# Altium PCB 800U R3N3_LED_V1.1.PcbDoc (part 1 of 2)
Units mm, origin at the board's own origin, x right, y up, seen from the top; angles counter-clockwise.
Board outline 308.48 x 220.22 mm, 4 copper layers (Top Layer, GND, Mid-Layer 2, Bottom Layer); 79 components, 48 nets, 220 pads, 97 vias.
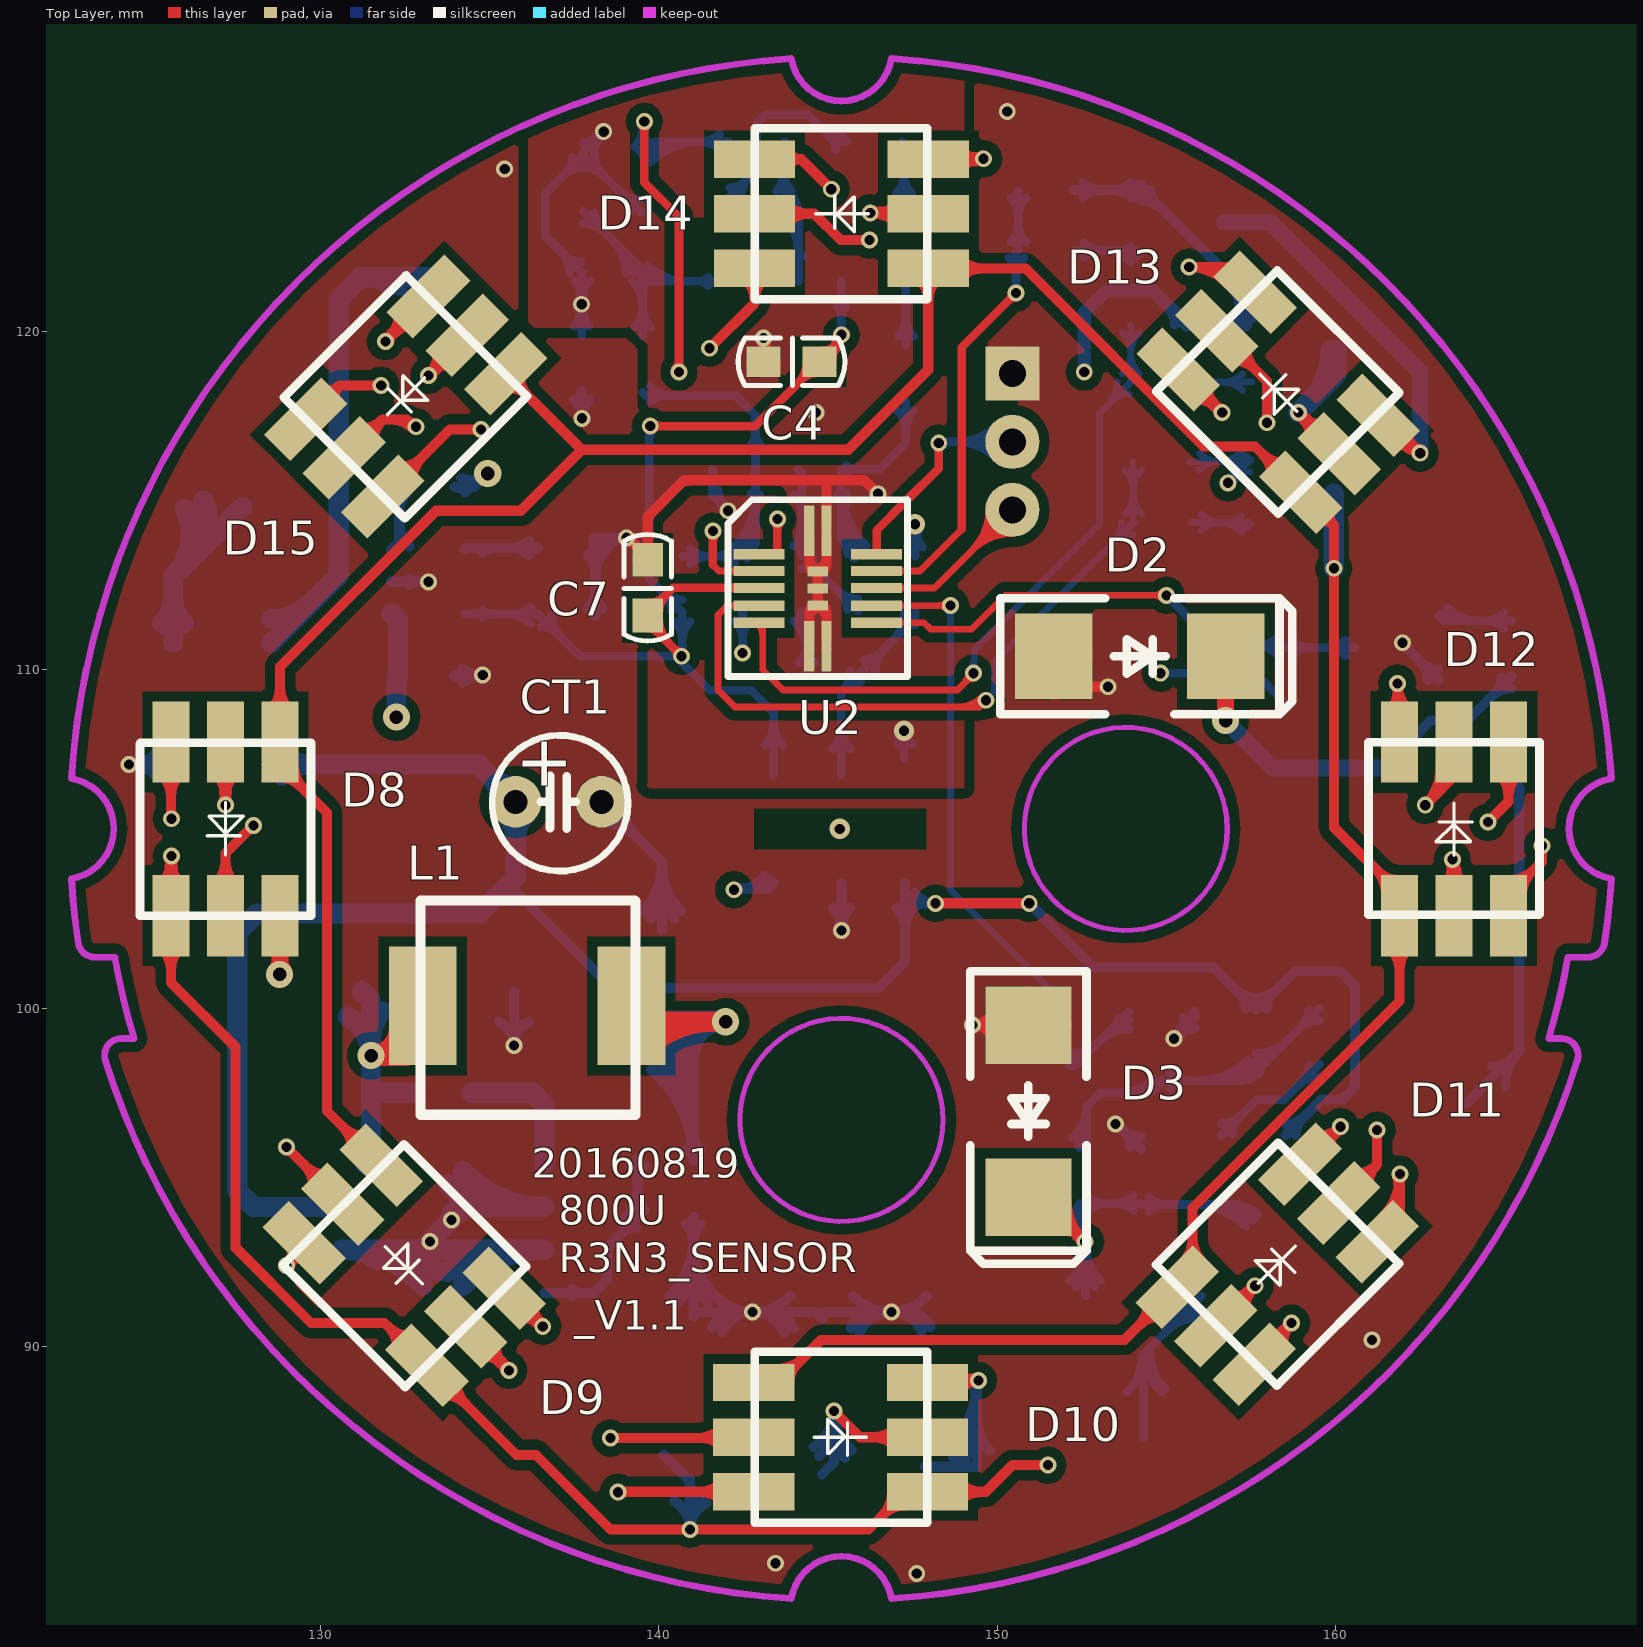
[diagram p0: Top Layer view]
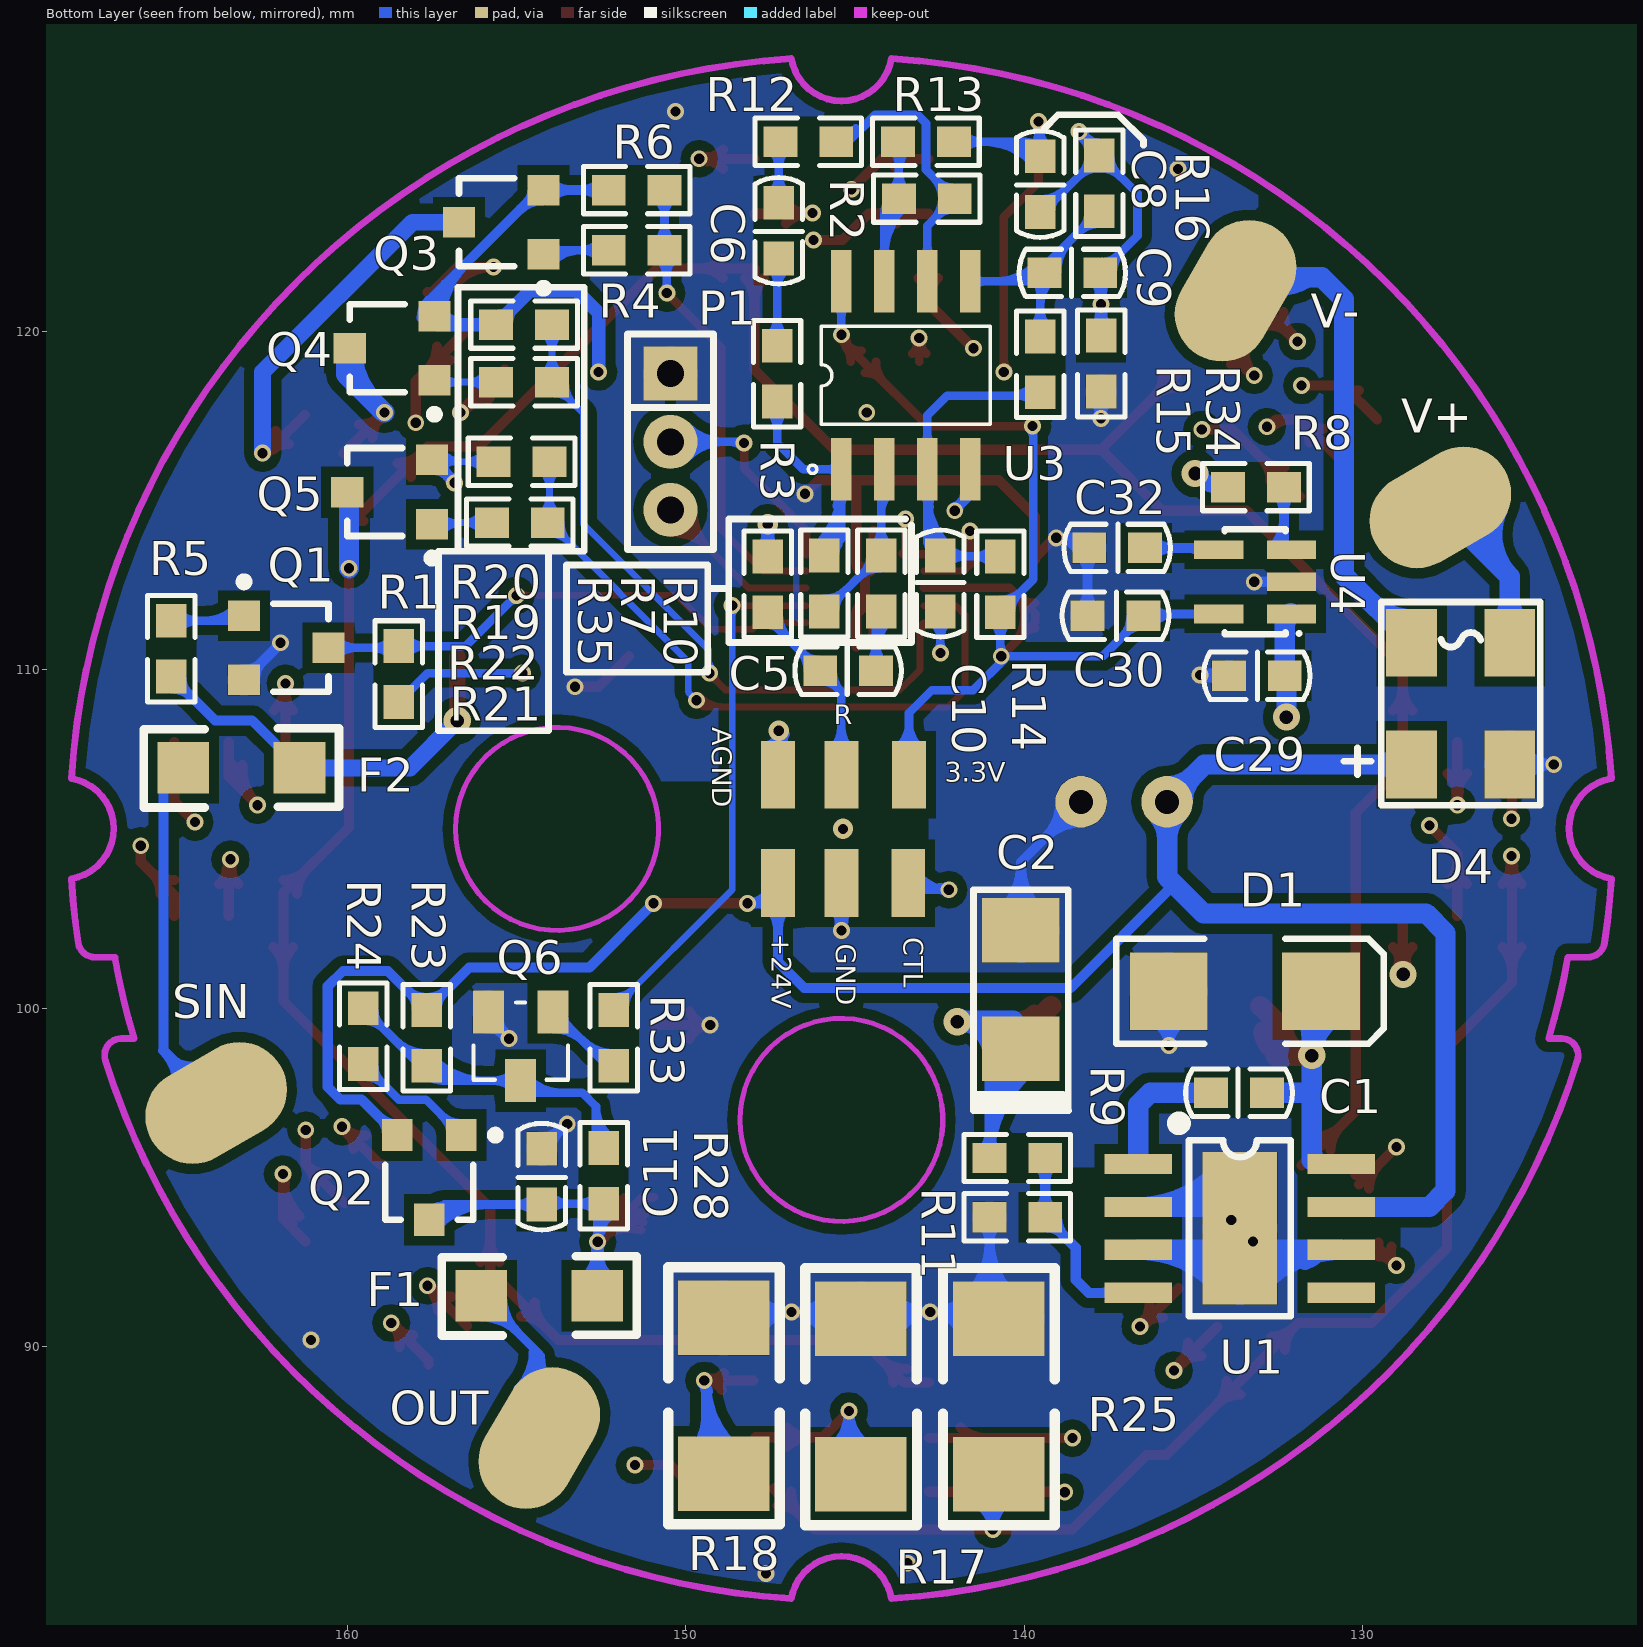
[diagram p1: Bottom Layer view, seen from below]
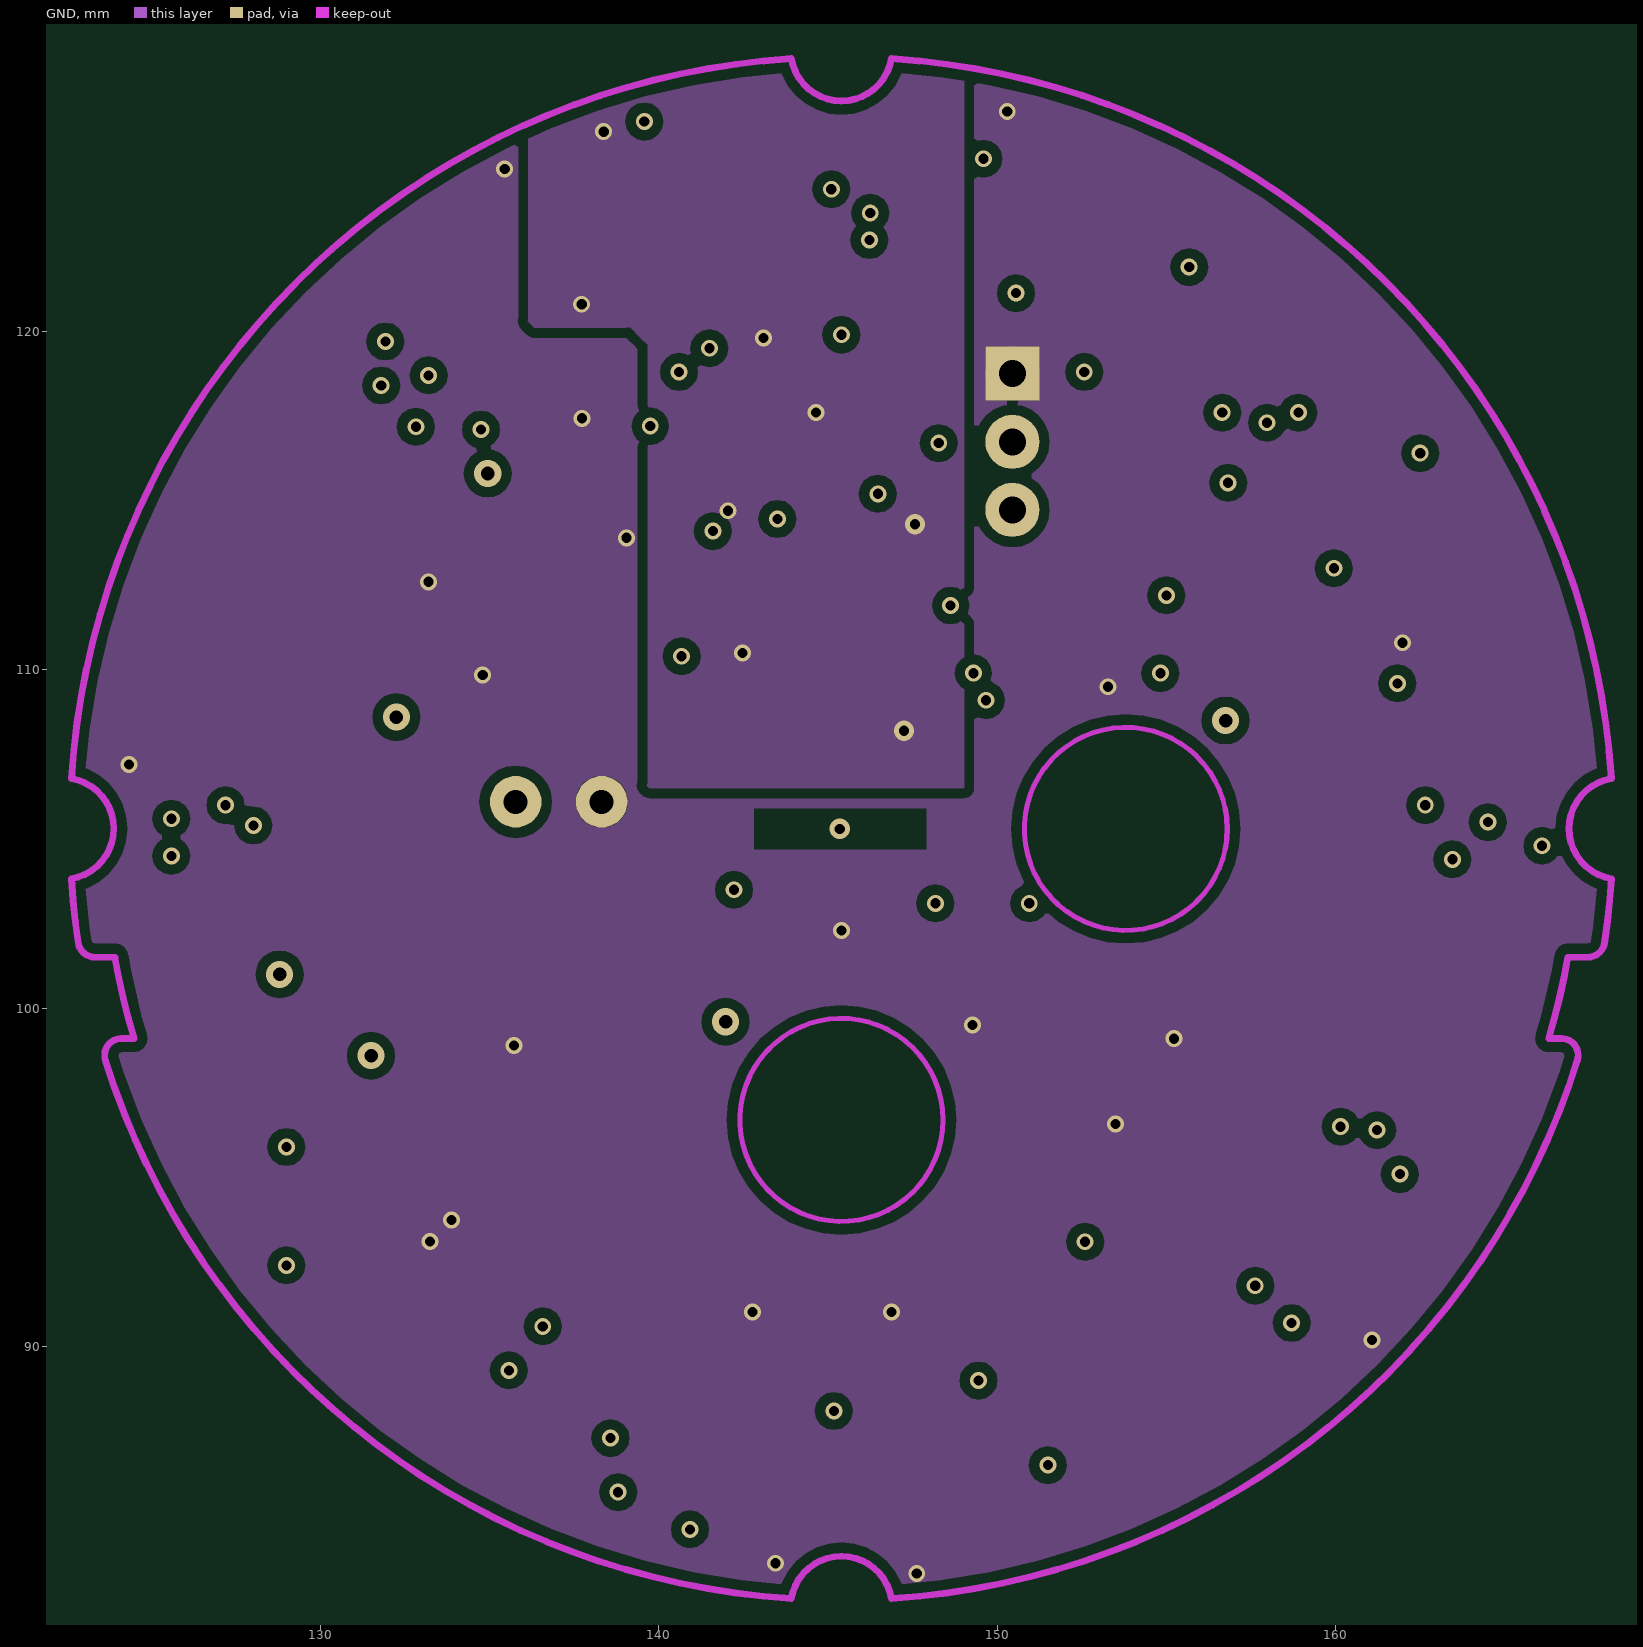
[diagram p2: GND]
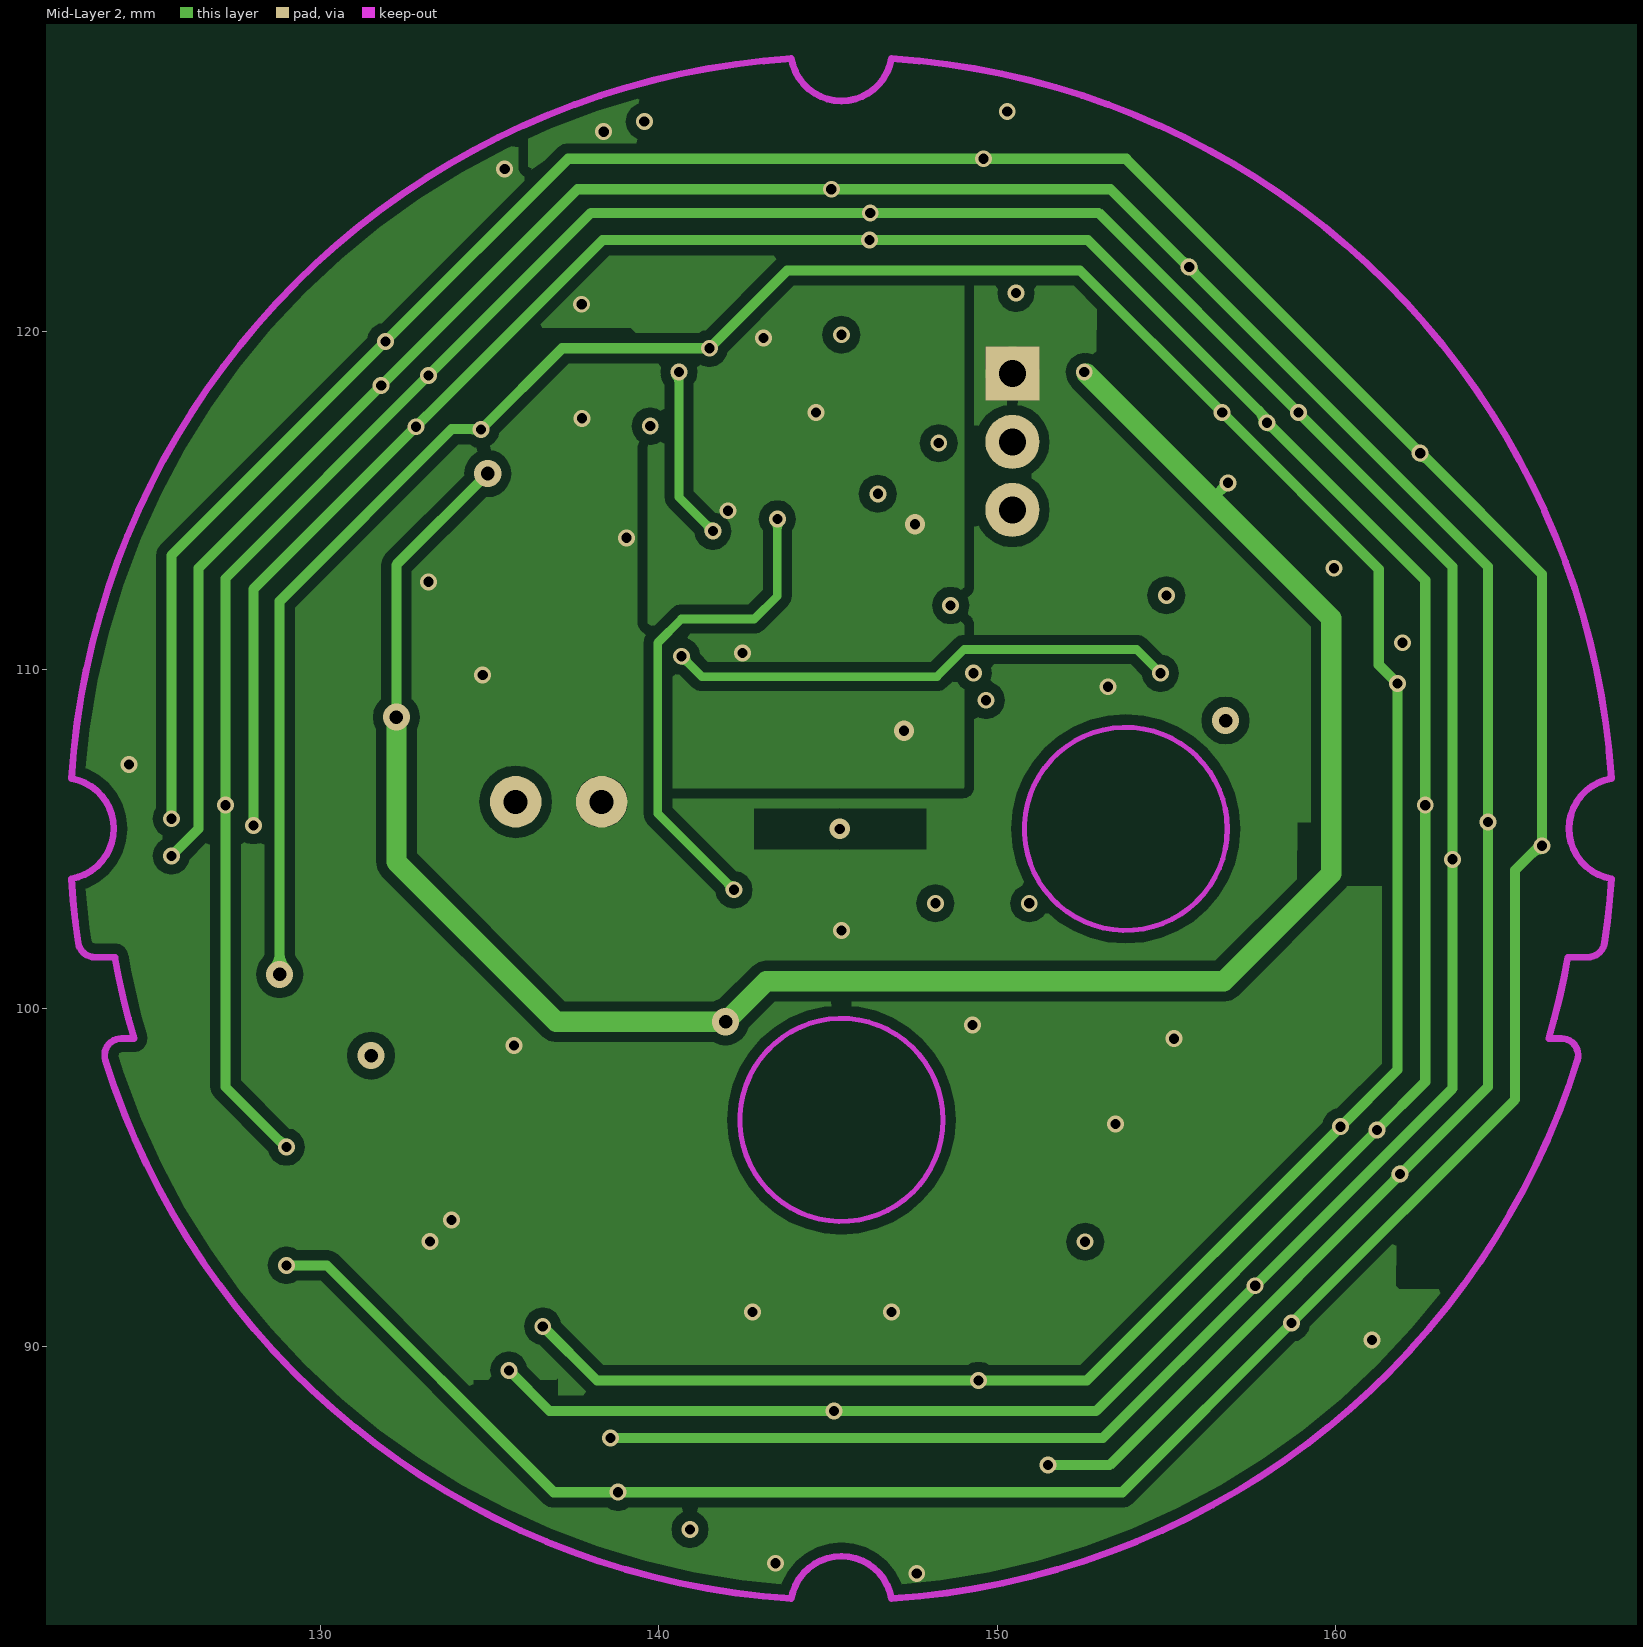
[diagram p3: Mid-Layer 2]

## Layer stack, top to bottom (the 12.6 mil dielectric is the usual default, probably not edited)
Top Layer: signal copper 0.0356
Dielectric: core 0.32, FR-4, Dk 4.8
GND: signal copper 0.0356
Dielectric: prepreg 0.32, FR-4, Dk 4.8
Mid-Layer 2: signal copper 0.0356
Dielectric: core 0.32, FR-4, Dk 4.8
Bottom Layer: signal copper 0.0356

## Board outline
-7.366,215.265 301.117,215.265 301.117,-4.191 300.736,-4.572 -6.985,-4.572 -7.366,-4.953

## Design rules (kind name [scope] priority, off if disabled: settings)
Clearance GND [InPolygon] p1: gap=0.3
Clearance Clearance_PAD [ISpad] p2: gap=0.17
Clearance [All] p3: gap=0.25
PolygonConnect [isvia] p1: connectstyle=Direct reliefconductorwidth=0.254 reliefentries=4 polygonreliefangle="90 Angle" airgapwidth=0.254
RoutingVias [All] p1: holewidth=0.3 width=0.5 viastyle="Through Hole" minholewidth=0.3 minwidth=0.5 maxholewidth=0.4 maxwidth=0.8
SilkToSolderMaskClearance SilkscreenOverComponentPads [IsPad] p1: minsilkscreentomaskgap=0.1 clearancetoexposedcopper=TRUE
SolderMaskExpansion [All] p1: expansion=0.102
UnConnectedPin [All] p1:
Width [All] p1: maxlimit=0.6 minlimit=0.2 preferedwidth=0.254 midlayer1_minwidth=0.254 midlayer1_maxwidth=0.254 midlayer2_prefwidth=0.2 minimp=50.000000 maximp=50.000000 favimp=50.000000
27 further rules are at their usual default settings.

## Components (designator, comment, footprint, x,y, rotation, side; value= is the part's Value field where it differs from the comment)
3.3V "" HOLE_SMD#1 143.4,106.9 r0 bottom locked
+24V "" HOLE_SMD#1 147.275,103.7 r180 bottom locked
AGND "" HOLE_SMD#1 147.275,106.9 r180 bottom locked
C1 "10nF" C0603 134.475,97.5 r180 bottom
C2 "钽电容" CT3528 140.075,100.5 r90 bottom
C4 "C106" C0603 144.75,119.1 r180 top
C5 "C104" C0603 146.025,109.975 r180 bottom
C6 "C104" C0603 147.25,122.15 r90 bottom
C7 "105" C0603 139.675,111.6 r90 top
C8 "C104" C0603 139.525,123.525 r90 bottom
C9 "C104" C0603 139.4,121.725 r180 bottom
C10 "C104" C0603 142.475,113.375 r270 bottom
C11 "104" C0603 154.25,94.2 r90 bottom
C29 "4.7uF" C0603 132.3,109.825 r0 bottom
C30 "4.7uF" C0603 136.475,111.6 r0 bottom
C32 "10nF" C0603 136.425,113.6 r0 bottom
CT1 "铝电解电容" RB0.1 135.775,106.1 r0 top
CTL "" HOLE_SMD#1 143.425,103.7 r180 bottom locked (schematic designator LED_CTL)
D1 "SS14" SMB 133.475,100.5 r180 bottom (schematic designator D4)
D2 "TVS36V" HSMA 151.675,110.4 r0 top
D3 "TVS36V" HSMA 150.925,99.5 r270 top
D4 "LX10M" "桥堆 3.8*3.5" 127.1,109 r0 bottom
D8 "5050RGB" 5050RGB 127.2,105.3 r90 top locked
D9 "5050RGB" 5050RGB 132.481,92.4 r135 top locked
D10 "5050RGB" 5050RGB 145.375,87.325 r180 top locked
D11 "5050RGB" 5050RGB 158.275,92.431 r225 top locked
D12 "5050RGB" 5050RGB 163.5,105.3 r270 top locked
D13 "5050RGB" 5050RGB 158.3,118.2 r315 top locked
D14 "5050RGB" 5050RGB 145.4,123.475 r0 top locked
D15 "5050RGB" 5050RGB 132.525,118.075 r45 top locked
F1 "FSMD012-1206-R" 1206 154.325,91.5 r180 bottom
F2 "FSMD012-1206-R" 1206 163.125,107.1 r0 bottom
GND "" HOLE_SMD#2 145.4,103.7 r180 top locked (schematic designator GND1)
L1 "68uH" L-6X6 132.625,100.1 r0 top
OUT "" HOLE_SMD#3 154.325,87.3 r300 bottom
P1 "3P 2.0mm" SIP3 150.45,119.275 r0 bottom
Q1 "MMBT5551" SOT-23#1 161.8,110.65 r270 bottom
Q2 "S8550" SOT-23#1 157.575,95 r0 bottom
Q3 "Si2301CDS" SOT-23#1 155.45,123.225 r90 bottom (schematic designator Q6)
Q4 "Si2301CDS" SOT-23#1 158.675,119.5 r90 bottom
Q5 "Si2301CDS" SOT-23#1 158.75,115.25 r90 bottom
Q6 "贴片三极管" SOT-23#2 154.875,98.9 r0 bottom
R "" HOLE_SMD#1 145.4,106.9 r180 bottom locked (schematic designator LED_R)
R1 "10K" R0603 158.475,110.7 r270 bottom
R2 "" R0603 142.05,123.925 r0 bottom
R3 "" R0603 147.3,117.925 r90 bottom
R4 "" R0603 152.275,122.4 r180 bottom
R5 "10K" R0603 165.2,109.8 r90 bottom
R6 "" R0603 152.275,124.175 r180 bottom
R7 "" R0603 145.9,111.725 r90 bottom
R8 "4K7" R0603 133.975,115.4 r180 bottom
R9 "" R0603 139.375,95.575 r0 bottom
R10 "" R0603 144.225,111.725 r90 bottom
R11 "" R0603 141.025,93.825 r180 bottom
R12 "" R0603 147.2,125.6 r180 bottom
R13 "" R0603 143.725,125.6 r180 bottom
R14 "" R0603 140.7,111.7 r90 bottom
R15 "" R0603 139.525,118.2 r90 bottom
R16 "" R0603 137.775,125.2 r270 bottom
R17 "" 2010 144.825,88.525 r270 bottom
R18 "" 2010 148.875,88.55 r270 bottom
R19 "" R0603 155.6,118.5 r180 bottom
R20 "" R0603 155.6,120.2 r180 bottom
R21 "" R0603 155.725,114.35 r180 bottom
R22 "" R0603 155.675,116.15 r180 bottom
R23 "10K" R0603 157.65,98.3 r90 bottom
R24 "10K" R0603 159.525,100 r270 bottom
R25 "" 2010 140.75,88.525 r270 bottom
R28 "0R" R0603 152.425,95.875 r270 bottom
R33 "2K" R0603 152.125,98.3 r90 bottom
R34 "" R0603 137.725,118.225 r90 bottom
R35 "" R0603 147.575,111.7 r90 bottom
SIN "" HOLE_SMD#3 163.875,97.2 r150 bottom
U1 "LM22674" SO-1.27-9/4.0 136.625,95.4 r270 bottom locked
U2 "C8051F300" QFN-11 144.7,112.4 r0 top locked
U3 "TP2312-SR" SO-8 145.4,115.925 r0 bottom locked (schematic designator U5)
U4 "SP6203/SP6205" SOT-23-5 133.175,112.6 r180 bottom
V+ "" HOLE_SMD#4 127.7,114.8 r195 bottom
V- "" HOLE_SMD#3 133.75,121.2 r300 bottom

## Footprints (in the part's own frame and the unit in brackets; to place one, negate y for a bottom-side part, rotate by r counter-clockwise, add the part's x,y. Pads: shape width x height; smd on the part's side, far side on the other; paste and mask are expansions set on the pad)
1206 [mil]
  rect 60x60 smd: 1(-67.5,0) 2(67.5,0)
  silkscreen extent -114,-46 114,46
2010 [mm]
  rect 2.2x2.7 smd: 1(-2.3,0) 2(2.3,0)
  silkscreen extent -3.8,-1.64 3.8,1.66
5050RGB [mm]
  rect 2.4x1.1 smd: 1(-2.565,1.613) 2(-2.565,0) 3(-2.565,-1.613) 4(2.565,-1.613) 5(2.565,0) 6(2.565,1.613)
  silkscreen extent -2.56,-2.53 2.54,2.53
C0603 [mm]
  rect 1x0.9 smd: 1(0,0) 2(1.65,0)
  silkscreen extent -0.75,-0.7 2.4,0.7
CT3528 [mil]
  rect 75x90 smd: 1(-66.85,0.75) 2(70.94,0.75)
  silkscreen extent -139,-54 118,56
HOLE_SMD#1 [mm]
  rect 1x2 smd: 1(0,0)
HOLE_SMD#2 [mm]
  rect 1x2 smd far side: 1(0,0)
HOLE_SMD#3 [mm]
  oval 4.4x2.8 smd: 1(0,0)
HOLE_SMD#4 [mm]
  oval 4.4x2.8 smd rot 45: 1(0,0)
HSMA [mil]
  rect 90x100 smd: 1(0,0) 2(200,0)
  silkscreen extent -62,-68 278,68
L-6X6 [mm]
  rect 2x3.5 smd: 1(0.403,-0.033) 2(6.571,-0.033)
  silkscreen extent 0.33,-3.25 6.69,3.08
QFN-11 [mm]
  rect 1.5x0.305 smd: 1(-1.737,1.018) 2(-1.737,0.518) 3(-1.737,0.018) 4(-1.737,-0.507) 5(-1.737,-1.007) 6(1.737,-1.007) 7(1.737,-0.507) 8(1.737,0.018) 9(1.737,0.518) 10(1.737,1.018)
  rect 0.305x1.5 smd: 11(-0.248,-1.705) 11(-0.248,1.705) 11(0.26,-1.705) 11(0.26,1.705)
  rect 0.6x0.3 smd: 11(0,-0.5) 11(0,0) 11(0,0.5)
  silkscreen extent -2.65,-2.6 2.65,2.63
R0603 [mm]
  rect 1x0.9 smd: 1(0,0) 2(1.65,0)
  silkscreen extent -0.75,-0.7 2.4,0.7
RB0.1 [mil]
  round 60 hole 28: 1(0,0) 2(100,0)
  silkscreen extent -27,-81 131,77
SIP3 [mm]
  rect 1.6x1.6 hole 0.8: 1(0,0.525)
  round 1.6 hole 0.8: 2(0,2.54) 3(0,4.55)
  silkscreen extent -1.28,-0.65 1.27,5.72
SMB [mm] "DO-214-AA/SMB; 2 C-Bend Leads; Body 5.3 x 3.6 mm, inc. leads (LxW)"
  rect 2.3x2.3 smd: 1(-2.25,0) 2(2.25,0)
  silkscreen extent -3.8,-1.55 4.1,1.55
SO-1.27-9/4.0 [mm]
  rect 0.6x2 smd: 1(0,0) 2(1.27,0) 3(2.54,0) 4(3.81,0) 5(3.81,6) 6(2.54,6) 7(1.27,6) 8(0,6)
  rect 4.5x2.2 smd: 9(1.905,3)
  silkscreen extent -1.35,1.05 4.5,4.5
SO-8 [mm]
  rect 0.6x1.85 smd: 1(0,0) 2(-1.27,0) 3(-2.54,0) 4(-3.81,0) 5(-3.81,-5.55) 6(-2.54,-5.55) 7(-1.27,-5.55) 8(0,-5.55)
  silkscreen extent -4.41,-4.23 0.98,0.12
SOT-23#1 [mm] "SOT-23; 3 Leads; Body 3.0 x 2."
  rect 0.9x0.95 smd: 1(-0.95,-1.25) 2(0.95,-1.25) 3(0,1.25)
  silkscreen extent -2.07,-1.38 1.3,1.25
SOT-23#2 [mm]
  rect 0.914x1.27 smd: 1(-0.953,-0.991) 2(0.953,-0.991) 3(0,1.041)
  silkscreen extent -1.4,-1.27 1.4,1.02
SOT-23-5 [mm]
  rect 1.45x0.55 smd: 1(1.075,-0.95) 2(1.075,0) 3(1.075,0.95) 4(-1.075,0.95) 5(-1.075,-0.95)
  silkscreen extent -0.9,-1.57 1.35,1.55
"桥堆 3.8*3.5" [mm]
  rect 1.5x2 smd: 1(1.45,1.8) 2(1.45,-1.8) 3(-1.45,-1.8) 4(-1.45,1.8)
  silkscreen extent -2.35,-3 3.45,3

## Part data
3.3V +24V AGND CTL GND OUT R SIN V+ V-: library part 焊盘
C1 C4 C5 C6 C8 C9 C10: library part Cap, "Capacitor"
C2 CT1: library part "Cap Pol1", "Polarized Capacitor (Radial)"
C7 C11: library part Cap, "贴片电容"
C29 C30 C32: library part CAP, "Capacitor"
D1: library part SMBJ6.0CA
D2 D3: library part "D Schottky", "贴片TVS"
D4: library part Bridge2, "贴片桥堆"
D8 D9 D10 D11 D12 D13 D14 D15: "RBG发光管"
F1 F2: library part "Fuse 2", "Fuse"
L1: library part 电感
P1: library part MHDR1X3, "插座"
Q1: library part NPN, "贴片NPN三极管"
Q2: "贴片PNP三极管"
Q3 Q4 Q5: library part P-MOSFET, "贴片MOS管"
Q6: library part NPN, "NPN三极管"
R1 R4 R5 R6 R17 R18 R19 R20 R21 R22 R23 R24 R25 R28 R33: library part "Res Semi", "贴片电阻"
R2 R3 R7 R9 R10 R11 R12 R13 R14 R15 R16 R34 R35: library part "Res Semi", "Semiconductor Resistor"
R8: library part Res1, "Resistor"
U1: library part 2674
U2: library part PIC16C505, "贴片芯片"
U3: library part LM833D, "Dual Low Noise, Audio Amplifier"

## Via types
v1: diameter 0.5, hole 0.3, Top Layer to Bottom Layer, 88 vias
v2: diameter 0.8, hole 0.4, Top Layer to Bottom Layer, 6 vias
v3: diameter 0.6, hole 0.3, Top Layer to Bottom Layer, 3 vias

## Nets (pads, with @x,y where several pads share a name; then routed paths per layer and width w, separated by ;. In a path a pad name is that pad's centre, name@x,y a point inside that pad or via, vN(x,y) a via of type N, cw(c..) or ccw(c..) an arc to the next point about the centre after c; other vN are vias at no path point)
3.3V: 3.3V.1 C4.1 C7.1 C30.1 R1.2 R14.1 U2.3 U3.8 U4.5 | length 68.1
  Top Layer w0.25: 140.418,112.418 U2.3@142.963,112.418
  Top Layer w0.254: C7.1@139.675,111.227 cw(c139.675,110.809) C7.1@139.97,111.105 ; C7.1@139.675,111.973 ccw(c139.675,112.692) 140.184,112.184 ; v1@139.775,117.2 142.85,117.2 C4.1@144.75,119.1 145.4,119.75 v1(145.4,119.9) ; v1@139.837,117.113 cw(c140.047,116.903) 140.047,117.2 cw(c140.047,117.497) v1@139.837,117.287 ; C7.1@139.998,111.55 ccw(c141.14,111.55) 140.332,110.743 ; C7.1@139.998,111.65 cw(c140.838,111.65) 140.244,112.244 ; 140.418,112.418 139.675,111.675 C7.1@139.675,111.6 139.675,111.4 v1(140.675,110.4) ; v1@140.552,110.4 ccw(c140.255,110.4) 140.465,110.61 ccw(c140.675,110.82) v1@140.675,110.523 ; 144.113,118.463 ccw(c143.477,119.1) C4.1@144.377,119.1 ; 144.234,118.584 cw(c144.7,118.118) C4.1@144.7,118.777 ; C4.1@144.8,119.423 ccw(c144.8,120.082) 145.266,119.616 ; C4.1@145.084,119.434 ccw(c144.618,119.9) v1@145.277,119.9 ; C4.1@145.123,119.1 cw(c146.023,119.1) v1@145.387,119.737 ; C4.1@145.228,119.461 ccw(c144.763,119.729) v1@145.281,119.868
  Mid-Layer 2 w0.254: v1@140.675,110.277 cw(c140.675,109.98) 140.885,110.19 cw(c141.095,110.4) v1@140.798,110.4 ; v1(140.675,110.4) 141.275,109.8 148.225,109.8 149.025,110.6 154.125,110.6 v1(154.825,109.9)
  Bottom Layer w0.254: U4.5@134.25,111.65 136.425,111.65 C30.1@136.475,111.6 137.675,110.4 v1(140.675,110.4) ; U4.5@134.805,111.545 cw(c135.057,111.293) 135.057,111.65 cw(c135.057,112.007) U4.5@134.805,111.755 ; 135.524,111.65 cw(c135.524,110.699) C30.1@136.197,111.372 ; 135.766,111.65 ccw(c135.766,112.259) C30.1@136.197,111.828 ; C30.1@136.525,111.277 cw(c136.525,110.618) 136.991,111.084 ; C30.1@136.848,111.6 ccw(c137.748,111.6) 137.112,110.963 ; v1@139.675,117.2 139.725,117.15 139.725,112.675 R14.1@140.7,111.7 v1@140.7,110.313 ; 139.725,116.843 cw(c140.107,116.843) v1@139.837,117.113 ; 140.063,112.337 ccw(c140.7,112.973) R14.1@140.7,112.073 ; 140.184,112.216 cw(c139.718,111.75) R14.1@140.377,111.75 ; R14.1@140.472,111.422 cw(c139.92,110.87) 140.7,110.87 cw(c141.48,110.87) R14.1@140.928,111.422 ; v1@140.588,110.313 141.501,109.4 142.725,109.4 143.4,108.725 3.3V.1@143.4,106.9 ; v1@140.588,110.487 ccw(c140.318,110.757) 140.7,110.757 ; 3.3V.1@143.136,107.763 ccw(c142.5,108.4) 143.4,108.4 ccw(c144.3,108.4) 3.3V.1@143.664,107.763 ; U3.8@145.278,120.728 cw(c144.982,120.432) 145.4,120.432 cw(c145.818,120.432) U3.8@145.522,120.728 ; v1@145.313,119.987 ccw(c145.103,120.197) 145.4,120.197 ccw(c145.697,120.197) v1@145.487,119.987 ; v1(145.4,119.9) U3.8@145.4,121.475 ; v1(154.825,109.9) 157.625,109.9 R1.2@158.475,109.05
  other v1: 139.75,117.2
+24V: +24V.1 CT1.1 D4.1 Q2.2 R23.2 U1.7 | length 77.6
  Top Layer w0.3: v1(148.175,103.1) v1(150.95,103.1)
  Bottom Layer w0.3: 135.563,103.663 138.625,100.6 146.5,100.6 147.275,101.375 +24V.1@147.275,103.15 ; +24V.1@147.028,102.953 cw(c146.43,102.355) 147.275,102.355 cw(c148.12,102.355) 147.522,102.953 cw(c147.879,102.596) 147.879,103.1 ; +24V.1@147.275,103.7 +24V.1@147.275,103.15 ; +24V.1@147.555,103.41 ccw(c148.175,103.875) v1(148.175,103.1) 147.325,103.1 +24V.1@147.275,103.15 ; v1(150.95,103.1) 152.85,101.2 156.4,101.2 R23.2@157.65,99.95 158.8,101.1 160.125,101.1 160.575,100.65 160.575,97.675 160.2,97.3 159.575,97.3 Q2.2@158.525,96.25 ; 157.053,100.547 ccw(c157.65,101.145) 157.65,100.3 ccw(c157.65,101.145) 158.247,100.547 ; 157.173,100.427 cw(c156.746,100) R23.2@157.35,100 ; R23.2@157.95,100 cw(c158.554,100) 158.127,100.427 ; Q2.2@158.525,96.575 ccw(c158.525,97.36) 159.08,96.805 ; Q2.2@158.825,96.275 cw(c159.489,96.275) 159.019,96.744
  Bottom Layer w0.6: D4.1@128.55,107.2 134.675,107.2 CT1.1@135.775,106.1 135.775,103.875 ; D4.1@128.868,106.882 cw(c129.636,106.114) 129.636,107.2 cw(c129.636,108.286) D4.1@128.868,107.518 ; U1.7@130.625,94.13 128.02,94.13 127.55,94.6 127.55,102.225 128.125,102.8 134.7,102.8 135.775,103.875 ; CT1.1@135.313,106.1 ccw(c134.198,106.1) 134.986,106.889 ccw(c135.775,107.677) CT1.1@135.775,106.562 ; CT1.1@135.448,105.773 cw(c134.66,104.985) 135.775,104.985 cw(c136.89,104.985) CT1.1@136.102,105.773 ; 135.563,103.663 135.775,103.875
ADCIN1: C8.2 R13.2 U2.2 | length 27.9
  Top Layer w0.2: 141.6,113.1 141.782,112.918 U2.2@142.963,112.918
  Top Layer w0.254: v1@139.488,126.113 cw(c139.278,125.903) 139.575,125.903 cw(c139.872,125.903) v1@139.662,126.113 ; v1(139.575,126.2) 139.575,124.4 140.6,123.375 v1(140.6,118.8) ; v1@140.488,118.887 ccw(c140.218,119.157) 140.6,119.157 ; v1@141.513,114.013 cw(c141.303,113.803) 141.6,113.803 cw(c141.897,113.803) v1@141.687,114.013 ; 141.6,113.1 v1(141.6,114.1)
  Mid-Layer 2 w0.254: v1@140.488,118.713 cw(c140.218,118.443) 140.6,118.443 ; v1(140.6,118.8) 140.6,115.1 v1(141.6,114.1) ; v1@141.477,114.1 ccw(c141.18,114.1) 141.39,114.31 ccw(c141.6,114.52) v1@141.6,114.223
  Bottom Layer w0.254: C8.2@139.297,125.453 ccw(c138.625,126.125) v1@139.575,126.125 ; C8.2@139.394,125.356 cw(c139.984,124.766) 139.984,125.6 ; v1@139.468,126.138 cw(c139.154,125.957) 139.505,125.863 ; v1@139.488,126.113 cw(c139.278,125.903) 139.575,125.903 cw(c139.872,125.903) v1@139.662,126.113 ; C8.2@139.525,125.175 C8.2@139.575,125.225 ; 139.529,125.953 cw(c139.752,125.893) v1@139.636,126.093 ; C8.2@139.574,125.176 cw(c140.597,124.153) 140.597,125.6 ; 139.575,125.884 ccw(c140.184,125.884) C8.2@139.753,125.453 ; v1(139.575,126.2) C8.2@139.575,125.225 ; C8.2@139.753,124.997 cw(c141.21,123.54) 141.21,125.6 ; R13.2@141.797,125.372 ccw(c141.245,124.82) 141.245,125.6 ccw(c141.245,126.38) R13.2@141.797,125.828 ; R13.2@142.075,125.6 139.95,125.6 C8.2@139.575,125.225
AGND: AGND.1 C4.2 C8.1 C9.2 C10.2 R16.1 R34.2 R35.2 U3.4 | length 36.2
  Top Layer w0.254: C4.2@142.89,119.346 ccw(c142.503,119.8) v1(143.1,119.8) ; v1@142.993,119.739 cw(c142.736,119.59) 143.023,119.513 cw(c143.31,119.436) v1@143.161,119.693 ; v1@143.013,119.713 cw(c142.803,119.503) 143.1,119.503 cw(c143.397,119.503) v1@143.187,119.713 ; v1@143.039,119.693 cw(c142.89,119.436) 143.177,119.513 cw(c143.464,119.59) v1@143.207,119.738 ; C4.2@143.1,119.1 v1(143.1,119.8) ; C4.2@143.31,119.346 cw(c143.697,119.8) v1(143.1,119.8)
  Bottom Layer w0.254: 137.113,122.362 cw(c136.477,121.725) C9.2@137.377,121.725 ; 137.138,124.563 cw(c137.775,123.927) 137.775,124.827 cw(c137.775,123.927) 138.412,124.563 ; 137.234,122.241 ccw(c137.7,122.707) C9.2@137.7,122.048 ; 137.259,124.684 ccw(c136.793,125.15) R16.1@137.452,125.15 ; R34.2@137.497,120.153 ccw(c136.945,120.705) 137.725,120.705 ccw(c138.505,120.705) R34.2@137.953,120.153 ; C9.2@137.522,121.497 cw(c137.031,121.006) v1@137.725,121.006 ; v1@137.618,120.739 cw(c137.288,120.548) 137.657,120.449 ; v1@137.618,120.862 ccw(c137.204,121.101) 137.666,121.225 ; v1@137.638,120.713 cw(c137.428,120.503) 137.725,120.503 cw(c138.022,120.503) v1@137.812,120.713 ; v1@137.638,120.887 ccw(c137.428,121.097) 137.725,121.097 ccw(c138.022,121.097) v1@137.812,120.887 ; R34.2@137.725,119.875 v1(137.725,120.8) 137.725,121.7 C9.2@137.75,121.725 136.65,122.825 136.65,124.075 R16.1@137.775,125.2 ; v1@137.725,120.885 cw(c138.59,120.885) C9.2@137.978,121.497 ; R16.1@137.775,125.573 ccw(c137.775,126.232) v1@138.241,125.766 ; 137.793,120.449 cw(c138.162,120.548) v1@137.832,120.738 ; 137.794,121.144 ccw(c138.154,121.047) v1@137.832,120.861 ; R16.1@138.04,125.65 ccw(c137.808,126.052) v1@138.256,125.932 ; R16.1@138.098,125.15 ccw(c138.757,125.15) 138.291,124.684 ; R16.1@138.098,125.25 cw(c138.998,125.25) v1@138.362,125.887 ; R16.1@138.216,125.635 cw(c138.488,125.478) v1@138.407,125.781 ; 138.228,125.655 ccw(c137.985,125.796) v1@138.256,125.868 ; v1@138.252,125.9 cw(c137.955,125.9) 138.165,125.69 cw(c138.375,125.48) v1@138.375,125.777 ; v1(138.375,125.9) 137.775,125.3 R16.1@137.775,125.2 ; 138.76,124.215 ccw(c139.525,124.98) C8.1@139.525,123.898 ; 139.062,123.913 cw(c138.724,123.575) C8.1@139.202,123.575 ; C8.1@139.525,123.525 139.45,123.525 R16.1@137.775,125.2 ; U3.4@141.59,115.925 141.59,115.16 v1(142.05,114.7) ; U3.4@141.763,115.3 ccw(c142.519,115.3) v1@141.984,114.766 ; 141.852,114.995 ccw(c142.18,115.185) v1@142.082,114.819 ; v1@141.927,114.7 ccw(c141.63,114.7) 141.84,114.91 ccw(c142.05,115.12) v1@142.05,114.823 ; C10.2@142.247,111.447 cw(c141.695,110.895) 142.475,110.895 cw(c143.255,110.895) C10.2@142.703,111.447 ; v1@142.388,110.587 ccw(c142.178,110.797) 142.475,110.797 ccw(c142.772,110.797) v1@142.562,110.587 ; v1(142.475,110.5) C10.2@142.475,111.725 ; v3@147.05,108.1 cw(c146.688,107.891) AGND.1@147.092,107.783 ; AGND.1@147.25,107.4 v3@147.25,108.3 ; v3@147.305,108.054 ccw(c147.709,108.162) AGND.1@147.5,107.8 ; R35.2@147.347,113.628 ccw(c146.795,114.18) 147.575,114.18 ccw(c148.355,114.18) R35.2@147.803,113.628 ; v3@147.429,114.208 cw(c147.04,113.961) R35.2@147.484,113.842 ; v3@147.453,114.178 cw(c147.157,113.882) 147.575,113.882 cw(c147.993,113.882) v3@147.697,114.178 ; v3@147.489,114.15 cw(c147.333,113.88) 147.634,113.961 ; 147.516,113.961 cw(c147.817,113.88) v3@147.661,114.15 ; R35.2@147.575,113.35 v3(147.575,114.3) ; R35.2@147.666,113.842 cw(c148.11,113.961) v3@147.721,114.208
  other v1: 144.65,117.6
  other v3: 147.25,108.2
B-: D8.3 D9.3 D10.3 D11.3 D12.3 D13.3 D14.3 D15.3 R18.2 | length 141
  Top Layer w0.3: D8.3@128.53,101.802 cw(c127.847,101.119) 128.813,101.119 cw(c129.779,101.119) D8.3@129.096,101.802 ; v2@128.615,101.168 ccw(c128.329,101.429) 128.703,101.529 ; v2@128.623,101.177 ccw(c128.165,101.635) D8.3@128.813,101.635 ; v2@128.675,101.217 ccw(c128.404,101.685) D8.3@128.927,101.545 ; 128.713,101.493 ccw(c129.153,101.611) v2@128.925,101.217 ; v2(128.8,101) 128.813,101.013 D8.3@128.813,102.735 ; D8.3@128.813,101.572 ccw(c129.372,101.572) v2@128.977,101.177 ; D8.3@128.934,101.571 ccw(c129.441,101.435) v2@129.007,101.14 ; D15.3@131.851,115.12 133.831,117.1 v1(134.75,117.1) ; D15.3@132.311,115.98 ccw(c132.311,116.946) 132.994,116.263 ccw(c133.677,115.58) D15.3@132.711,115.58 ; D9.3@135.436,91.726 v1@136.562,90.6 ; D9.3@135.902,90.867 cw(c135.917,89.955) v1@136.562,90.6 ; D9.3@136.295,91.26 ccw(c137.207,91.245) v1@136.562,90.6 ; 136.349,90.723 ccw(c136.481,90.951) v1@136.549,90.697 ; 136.382,90.78 ccw(c136.575,90.973) v1@136.575,90.7 ; 136.431,90.827 ccw(c136.673,90.967) v1@136.601,90.697 ; v1(136.575,90.6) v1@136.562,90.6 ; v1(141.5,119.5) 142.835,120.835 D14.3@142.835,121.862 ; D14.3@142.552,121.579 cw(c141.869,120.896) 142.835,120.896 cw(c143.8,120.896) D14.3@143.117,121.579 ; D10.3@148.003,89 v1(149.45,89) ; D10.3@148.873,89.221 ccw(c149.406,89.754) v1@149.406,89 ; D10.3@148.924,88.717 cw(c149.45,88.37) v1(149.45,89) ; 149.187,89.059 ccw(c149.26,89.329) v1@149.4,89.087 ; v1@149.388,88.938 v1(149.45,89) ; D13.3@155.345,118.874 156.619,117.6 v1(156.65,117.6) ; D13.3@155.805,118.014 cw(c155.805,117.048) 156.488,117.731 cw(c157.171,118.414) D13.3@156.205,118.414 ; 156.374,117.928 ccw(c156.804,118.176) v1@156.676,117.697 ; 156.389,117.788 cw(c156.213,117.483) v1@156.553,117.574 ; 156.426,117.793 ccw(c156.65,118.016) v1@156.65,117.7 ; D11.3@158.949,95.386 159.036,95.386 v1(160.15,96.5) cw(c159.523,97.127) D11.3@159.444,96.244 ; D11.3@159.808,95.845 cw(c160.564,95.845) v1@160.029,96.379 ; 159.938,96.221 cw(c160.277,96.025) v1@160.176,96.403 ; D12.3@161.604,108.798 ccw(c161.071,109.331) 161.825,109.331 ; D12.3@161.825,107.928 v1(161.825,109.6) ; v1@161.887,109.538 v1(161.825,109.6) ; D12.3@162.164,108.804 cw(c162.929,109.6) v1(161.825,109.6)
  Mid-Layer 2 w0.3: v2@128.623,101.177 ccw(c128.196,101.604) 128.8,101.604 ccw(c129.404,101.604) v2@128.977,101.177 ; v2(128.8,101) 128.8,112.025 133.887,117.112 v1@134.612,117.112 ; 134.478,117.112 cw(c134.478,116.828) v1@134.679,117.029 ; v1(134.75,117.1) 137.15,119.5 v1(141.5,119.5) 143.8,121.8 152.45,121.8 v1(156.65,117.6) 161.275,112.975 161.275,110.15 v1(161.825,109.6) 161.825,98.175 v1(160.15,96.5) 152.65,89 v1(149.45,89) 138.175,89 v1(136.575,90.6)
  Bottom Layer w0.3: R18.2@147.875,86.45 149.4,86.45 v1@149.4,88.95 ; R18.2@148.499,86.965 ccw(c146.762,88.95) v1@149.4,88.95 ; R18.2@148.697,86.739 ccw(c147.341,88.289) 149.4,88.289 ; R18.2@148.895,86.513 ccw(c147.92,87.627) 149.4,87.627 ; 149.343,88.681 cw(c149.707,88.603) v1@149.504,88.916 ; 149.4,87.88 ccw(c150.755,87.88) R18.2@149.797,86.922 ; 149.4,88.638 cw(c149.812,88.638) v1@149.521,88.929 ; v1(149.45,89) v1@149.4,88.95
BLUE: D8.4 D9.4 D10.4 D11.4 D12.4 D13.4 D14.4 D15.4 Q5.3 | length 121.2
  Top Layer w0.3: D8.4@128.53,108.798 ccw(c127.847,109.481) 128.813,109.481 ccw(c129.779,109.481) D8.4@129.096,108.798 ; D8.4@128.813,106.815 cw(c128.813,105.978) 129.405,106.57 ; D8.4@129.213,107.215 ccw(c130.307,107.215) 129.533,106.442 ; D9.4@130.948,95.814 ccw(c129.982,95.814) 130.665,96.497 ccw(c131.348,97.18) D9.4@131.348,96.214 ; D9.4@131.808,95.355 130.2,96.962 130.2,105.775 128.813,107.162 D8.4@128.813,107.865 128.813,110.088 133.425,114.7 135.925,114.7 137.737,116.513 ; D15.4@135.48,118.349 cw(c135.48,117.383) 136.162,118.066 cw(c136.845,118.749) D15.4@135.88,118.749 ; D15.4@135.48,118.749 137.728,116.5 145.6,116.5 147.965,118.865 D14.4@147.965,121.862 150.838,121.862 156.1,116.6 157.619,116.6 D13.4@158.974,115.245 159.95,114.269 ; D10.4@142.81,88.938 143.538,88.938 144.8,90.2 153.763,90.2 D11.4@155.32,91.758 155.775,92.212 155.775,94.1 161.887,100.212 D12.4@161.887,102.735 161.887,103.413 159.95,105.35 v1(159.95,113) 159.95,114.269 ; D10.4@143.46,89.338 ccw(c143.46,90.493) 144.276,89.676 ; D10.4@143.86,88.938 cw(c144.636,88.938) 144.087,89.487 ; D14.4@147.683,121.579 cw(c147,120.896) 147.965,120.896 cw(c148.931,120.896) D14.4@148.248,121.579 ; D14.4@148.898,121.579 cw(c149.581,120.896) 149.581,121.862 cw(c149.581,122.828) D14.4@148.898,122.145 ; D11.4@154.461,91.298 cw(c153.495,91.298) 154.178,90.615 cw(c154.861,89.932) D11.4@154.861,90.898 ; D11.4@155.497,92.5 ccw(c154.827,93.17) 155.775,93.17 ; 155.775,93.195 ccw(c156.758,93.195) D11.4@156.063,92.5 ; D13.4@158.114,115.705 ccw(c157.148,115.705) 157.831,116.388 ccw(c158.514,117.071) D13.4@158.514,116.105 ; D13.4@159.519,114.395 cw(c159.619,113.938) 159.95,114.269 ; D13.4@159.824,114.7 ccw(c160.281,114.6) 159.95,114.269 ; 161.184,104.116 cw(c160.453,103.385) D12.4@161.487,103.385 ; 161.253,104.047 ccw(c161.887,104.682) D12.4@161.887,103.785 ; D12.4@161.604,101.802 cw(c160.921,101.119) 161.887,101.119 cw(c162.853,101.119) D12.4@162.17,101.802
  Bottom Layer w0.3: v1(159.95,113) v1@160,113.05
  Bottom Layer w0.6: v1(159.95,113) Q5.3@159.95,115.2
G-: D8.2 D9.2 D10.2 D11.2 D12.2 D13.2 D14.2 D15.2 R17.2 | length 140.7
  Top Layer w0.3: D8.2@126.917,103.667 ccw(c126.234,104.35) 127.2,104.35 ccw(c128.166,104.35) D8.2@127.483,103.667 ; D8.2@127.2,102.735 127.2,104.575 v1(128.025,105.4) ; D15.2@130.711,116.261 131.85,117.4 ; D15.2@131.172,117.121 ccw(c131.176,118.074) 131.85,117.4 ; D15.2@131.571,116.722 cw(c132.524,116.726) 131.85,117.4 ; 132.056,117.4 cw(c132.056,116.412) v1@132.754,117.111 ; 132.558,117.392 ccw(c132.825,117.659) v1@132.825,117.281 ; v1@132.85,117.1 132.55,117.4 131.85,117.4 ; D9.2@134.295,90.586 135.575,89.306 v1(135.575,89.3) ; D9.2@134.755,89.726 cw(c134.755,88.761) 135.438,89.444 cw(c136.12,90.126) D9.2@135.155,90.126 ; 135.278,89.536 cw(c135.062,89.163) v1@135.478,89.274 ; 135.356,89.584 ccw(c135.705,89.786) v1@135.601,89.397 ; 135.4,89.481 cw(c135.219,89.3) v1@135.475,89.3 ; D14.2@142.835,123.475 144.6,123.475 145.375,122.7 v1(146.225,122.7) ; D14.2@143.767,123.192 cw(c144.45,122.509) 144.45,123.475 cw(c144.45,124.441) D14.2@143.767,123.758 ; v1(145.175,88.1) 145.95,87.325 D10.2@147.94,87.325 ; D10.2@147.008,87.042 ccw(c146.325,86.359) 146.325,87.325 ccw(c146.325,88.291) D10.2@147.008,87.608 ; D13.2@156.486,120.014 157.975,118.525 v1(157.975,117.3) ; D13.2@156.946,119.154 cw(c156.946,118.189) 157.628,118.872 cw(c158.311,119.554) D13.2@157.346,119.554 ; D11.2@160.089,94.245 161.225,95.381 ; D11.2@160.551,95.105 ccw(c160.558,96.048) 161.225,95.381 ; D11.2@160.949,94.707 cw(c161.892,94.714) 161.225,95.381 ; v1(161.225,96.4) 161.225,95.381 ; D12.2@163.101,107.191 cw(c161.555,107.095) v1(162.65,106) 163.5,106.85 D12.2@163.5,107.865 ; 163.121,106.471 ccw(c162.441,107.15) D12.2@163.4,107.209
  Mid-Layer 2 w0.3: v1(128.025,105.4) 128.025,112.381 138.344,122.7 v1(146.225,122.7) 152.681,122.7 157.975,117.406 v1(157.975,117.3) 158,117.3 162.65,112.65 v1(162.65,106) 162.65,97.825 v1(161.225,96.4) 152.925,88.1 v1(145.175,88.1) 136.775,88.1 v1(135.575,89.3) ; 157.729,117.652 cw(c157.377,117.3) v1@157.875,117.3 ; v1@157.975,117.2 cw(c157.975,116.898) 158.188,117.112
  Bottom Layer w0.3: R17.2@144.579,87.035 ccw(c143.926,88.1) v1(145.175,88.1) ; R17.2@144.735,86.779 ccw(c144.254,87.564) 145.175,87.564 ; R17.2@144.825,86.225 145.175,86.575 v1(145.175,88.1) ; 145.175,87.438 ccw(c146.138,87.438) R17.2@145.503,86.714 ; R17.2@145.701,86.94 cw(c146.718,88.1) v1(145.175,88.1)
  other v1: 132.825,117.181
GND: C2.2 C7.2 C11.2 C29.2 C30.2 C32.2 CT1.2 D1.1 D2.1 D3.1 D4.4 GND.1 P1.1 Q1.2 Q6.2 R11.1 R17.1 R18.1 R25.1 R34.1 U1.2 U1.3 U1.6 U1.9 U2.11 U4.2 | length 125.8
  Top Layer w0.3: v1@139.1,113.9 C7.2@139.673,113.327 ; C7.2@139.675,113.25 139.675,114.525 140.75,115.6 144.55,115.6 146.075,115.6 v1(146.475,115.2) ; U2.11@144.453,110.695 144.453,111.653 ; U2.11@144.453,114.105 144.453,113.148 ; 144.956,111.644 cw(c145.212,111.9) U2.11@144.85,111.9 ; 144.956,113.156 ccw(c145.212,112.9) U2.11@144.85,112.9 ; U2.11@144.961,110.695 144.961,111.64 U2.11@144.7,111.9 ; 144.961,113.167 cw(c144.583,113.167) U2.11@144.85,112.9 ; 144.961,115.5 U2.11@144.961,114.105 144.961,113.161 ; D3.1@149.889,99.099 ccw(c149.275,98.829) v1(149.275,99.5) ; D3.1@149.889,99.901 cw(c149.275,100.171) v1(149.275,99.5) ; D3.1@150.925,99.5 v1(149.275,99.5) ; D2.1@151.675,110.4 152.575,109.5 v1(153.275,109.5) ; 144.453,111.653 ccw(c144.217,111.888) U2.11@144.55,111.9 ; 144.453,111.653 U2.11@144.7,111.9 ; 144.453,113.147 cw(c144.217,112.912) U2.11@144.55,112.9 ; 144.453,113.148 U2.11@144.7,112.9 ; U2.11@144.55,111.9 ccw(c144.785,111.665) 144.453,111.665 cw(c144.785,111.665) U2.11@144.55,111.9 ; U2.11@144.55,112.9 cw(c144.785,113.135) 144.453,113.135 ccw(c144.785,113.135) U2.11@144.55,112.9 ; U2.11@144.7,111.9 U2.11@144.7,112.9 ; U2.11@144.7,112.9 144.961,113.161 ; U2.11@144.85,111.9 cw(c144.583,111.633) 144.961,111.633 ccw(c144.583,111.633) U2.11@144.85,111.9 ; U2.11@144.85,112.9 ccw(c144.598,113.16) 144.961,113.16
  Bottom Layer w0.3: D4.4@125.193,106.811 ccw(c124.35,106.092) v1(124.35,107.2) ; D4.4@125.193,107.589 cw(c124.35,108.308) v1(124.35,107.2) ; D4.4@125.65,107.2 v1(124.35,107.2) ; U4.2@132.1,112.6 v1(133.2,112.6) ; U4.2@132.638,112.512 cw(c132.852,112.298) 132.852,112.6 cw(c132.852,112.902) U4.2@132.638,112.688 ; C29.2@133.95,109.825 134.775,109.825 v1(134.8,109.85) ; C29.2@134.212,109.613 cw(c134.724,109.101) 134.724,109.825 cw(c134.724,110.549) C29.2@134.212,110.037 ; 134.453,109.898 ccw(c134.555,110.275) v1@134.75,109.937 ; 134.498,109.825 ccw(c134.498,110.152) v1@134.729,109.921 ; 134.557,109.78 ccw(c134.491,110.028) v1@134.713,109.9 ; D1.1@135.287,99.601 cw(c134.945,98.9) v1(135.725,98.9) ; D1.1@135.725,100.5 v1(135.725,98.9) ; D1.1@136.163,99.601 ccw(c136.505,98.9) v1(135.725,98.9) ; R34.1@137.513,117.963 cw(c137.001,117.451) 137.725,117.451 cw(c138.449,117.451) R34.1@137.937,117.963 ; 137.725,117.688 ccw(c137.989,117.688) v1@137.802,117.501 ; R34.1@137.725,118.225 137.725,117.424 v1(137.732,117.431) ; 137.79,117.694 ccw(c138.062,117.621) v1@137.818,117.481 ; C30.2@137.913,111.812 ccw(c137.401,112.324) 138.125,112.324 ccw(c138.849,112.324) C30.2@138.337,111.812 ; C32.2@137.913,113.388 cw(c137.401,112.876) 138.125,112.876 cw(c138.849,112.876) C32.2@138.337,113.388 ; C30.2@138.125,111.6 138.125,113.55 C32.2@138.075,113.6 138.075,113.875 138.1,113.9 v1(139.05,113.9) ccw(c139.05,113.187) C32.2@138.399,113.478 ; C32.2@138.125,113.6 cw(c138.587,113.394) 138.587,113.9 ; CT1.2@138.315,105.488 cw(c138.315,104.011) 139.36,105.055 cw(c140.404,106.1) CT1.2@138.927,106.1 ; CT1.2@138.315,106.1 140.094,104.321 C2.2@140.094,102.302 ; C2.2@139.527,102.869 ccw(c138.157,104.239) 140.094,104.239 ccw(c142.031,104.239) C2.2@140.661,102.869 ; C2.2@139.739,102.657 ccw(c138.881,103.515) 140.094,103.515 ccw(c141.307,103.515) C2.2@140.449,102.657 ; R25.1@140.328,91.497 ccw(c138.646,93.179) 141.025,93.179 ; R25.1@140.54,91.285 ccw(c139.37,92.455) 141.025,92.455 ; R11.1@140.813,93.613 cw(c140.301,93.101) 141.025,93.101 cw(c141.749,93.101) R11.1@141.237,93.613 ; R25.1@141.025,90.9 R11.1@141.025,93.825 ; R25.1@141.025,91.025 v1(142.775,91.025) ; 141.025,92.334 ccw(c142.509,92.334) R25.1@141.46,91.285 ; 141.025,93.058 ccw(c143.233,93.058) R25.1@141.672,91.497 ; R25.1@141.593,90.559 cw(c142.312,90.238) 142.312,91.025 ; R25.1@141.681,91.487 ccw(c142.775,92.55) v1(142.775,91.025) ; R25.1@141.867,90.437 cw(c142.775,90.03) v1(142.775,91.025) ; 143.245,91.025 cw(c143.245,90.209) R17.1@143.985,90.552 ; R17.1@143.713,90.426 ccw(c142.775,89.991) v1(142.775,91.025) ; R17.1@143.9,91.494 cw(c142.775,92.61) v1(142.775,91.025) ; R17.1@144.825,90.825 144.625,91.025 v1(142.775,91.025) ; R17.1@144.825,91.025 v1(146.875,91.025) ; GND.1@145.153,102.953 cw(c144.555,102.355) 145.4,102.355 cw(c146.245,102.355) GND.1@145.647,102.953 ; v1@145.313,102.35 ccw(c145.062,102.495) 145.342,102.57 ; v1(145.4,102.3) GND.1@145.4,103.7 ; 145.458,102.57 ccw(c145.738,102.495) v1@145.487,102.35 ; R17.1@145.665,90.552 cw(c146.405,90.209) 146.405,91.025 ; R17.1@145.75,91.494 ccw(c146.875,92.61) v1(146.875,91.025) ; R17.1@145.937,90.426 cw(c146.875,89.991) v1(146.875,91.025) ; 147.342,91.025 cw(c147.342,90.264) R18.1@148.034,90.58 ; R18.1@147.6,91.05 147.575,91.025 v1(146.875,91.025) ; R18.1@147.761,90.456 ccw(c146.875,90.051) v1(146.875,91.025) ; R18.1@147.922,91.488 cw(c146.875,92.438) v1(146.875,91.025) ; v1@153.5,96.475 cw(c153.5,96.173) 153.713,96.387 ; v1(153.5,96.575) 153.5,96.6 C11.2@154.25,95.85 ; v1@153.597,96.601 ccw(c153.942,96.694) 153.763,96.383 ; v1@153.653,96.447 ccw(c154.25,97.045) C11.2@154.25,96.2 ; 153.773,96.327 cw(c153.346,95.9) C11.2@153.95,95.9 ; v1@155.199,99.197 ccw(c155.119,99.495) Q6.2@155.387,99.341 ; v1(155.225,99.1) 155.225,99.125 155.827,99.727 Q6.2@155.827,99.891 ; v1@155.278,99.178 cw(c155.827,98.628) Q6.2@155.827,99.406 ; v1@155.313,99.213 ccw(c154.814,99.713) Q6.2@155.52,99.713 ; v1@155.322,99.074 cw(c155.69,98.975) Q6.2@155.499,99.306 ; v1@155.325,99.1 cw(c155.627,99.1) Q6.2@155.413,99.313 ; v1@161.963,110.787 Q1.2@163.05,109.7 ; v1@162.075,110.8 ccw(c162.377,110.8) 162.163,110.587 ; 162.495,110.255 cw(c161.94,109.7) Q1.2@162.725,109.7 ; 162.556,110.194 ccw(c163.025,110.664) Q1.2@163.025,110
  Bottom Layer w0.6: U1.6@131.325,92.86 ccw(c131.861,93.169) 131.701,92.572 ; 131.994,92.86 cw(c131.994,90.842) U1.9@133.478,92.209 ; U1.9@132.757,92.86 ccw(c132.757,93.593) U1.9@133.275,93.075 ; U1.9@133.037,91.803 ccw(c130.625,89.581) U1.6@130.625,92.86 132.99,92.86 v1(133.24,93.11) ; U1.9@133.205,93.075 ccw(c133.723,93.593) U1.9@133.723,92.86 ; U1.9@133.772,92.209 cw(c135.256,90.842) 135.256,92.86 ; U1.9@133.772,94.781 ccw(c135.256,96.148) 135.256,94.13 ; U1.9@133.828,93.754 cw(c134.26,93.694) U1.9@134.26,94.13 ; U1.9@133.842,93.783 cw(c134.68,92.945) U1.9@134.68,94.13 ; U1.9@134.213,91.803 cw(c136.625,89.581) U1.3@136.625,92.86 133.49,92.86 v1(133.24,93.11) ; U1.9@134.213,95.187 ccw(c136.625,97.409) U1.2@136.625,94.13 U1.9@134.26,94.13 ; v1(133.24,93.11) U1.9@133.625,93.495 v1(133.878,93.748) U1.9@134.26,94.13
  other v1: 147.625,83.3 143.45,83.6 161.075,90.2 161.975,110.8 135.45,124.8 150.3,126.5
GREEN: D8.5 D9.5 D10.5 D11.5 D12.5 D13.5 D14.5 D15.5 Q4.3 | length 143.2
  Top Layer w0.3: D8.5@126.917,106.933 cw(c126.234,106.25) 127.2,106.25 cw(c128.166,106.25) D8.5@127.483,106.933 ; v1@127.113,106.05 ccw(c126.713,106.281) 127.16,106.401 ; v1(127.2,106) D8.5@127.2,107.865 ; 127.24,106.401 ccw(c127.687,106.281) v1@127.287,106.05 ; v1(129,95.9) D9.5@130.108,94.792 ; 129.511,95.389 cw(c128.796,94.674) D9.5@129.807,94.674 ; 129.557,95.343 ccw(c130.207,95.994) D9.5@130.207,95.074 ; v1@133.282,118.782 cw(c133.879,118.184) D15.5@133.879,119.029 ; v1@133.297,118.674 cw(c133.629,118.585) 133.457,118.883 ; D15.5@133.48,119.414 cw(c132.523,119.377) v1(133.2,118.7) 134.339,119.839 D15.5@134.339,119.889 ; v1(138.575,87.3) D10.5@142.81,87.3 ; 141.134,87.3 ccw(c141.134,88.351) D10.5@141.877,87.608 ; 141.254,87.3 cw(c141.254,86.42) D10.5@141.877,87.042 ; v1(146.25,123.5) 146.275,123.475 D14.5@147.965,123.475 ; v1@146.3,123.587 ccw(c146.506,123.943) 146.613,123.545 ; v1@146.321,123.571 ccw(c146.552,123.802) 146.552,123.475 ; D14.5@147.033,123.192 ccw(c146.35,122.509) 146.35,123.475 ccw(c146.35,124.441) D14.5@147.033,123.758 ; D11.5@156.461,90.617 157.625,91.781 v1(157.625,91.8) ; D11.5@156.921,91.477 ccw(c156.921,92.442) 157.603,91.76 ccw(c158.286,91.077) D11.5@157.321,91.077 ; 157.377,91.629 ccw(c157.215,91.91) v1@157.528,91.826 ; 157.441,91.597 ccw(c157.238,91.8) v1@157.525,91.8 ; v1@158.874,117.503 cw(c158.788,117.184) 159.075,117.349 ; v1(158.9,117.6) D13.5@160.114,116.386 ; v1@158.997,117.626 ccw(c159.316,117.712) 159.151,117.425 ; D13.5@159.254,116.846 ccw(c158.289,116.846) 158.972,117.528 ccw(c159.654,118.211) D13.5@159.654,117.246 ; D12.5@163.217,103.668 ccw(c162.535,104.35) v1@163.5,104.35 ; v1@163.363,104.35 cw(c162.973,104.125) 163.408,104.008 ; v1@163.379,104.329 cw(c163.088,104.038) 163.5,104.038 ; v1@163.4,104.313 cw(c163.219,104) 163.569,104.094 ; v1(163.45,104.4) v1@163.5,104.35 ; D12.5@163.5,102.735 v1@163.5,104.35 ; D12.5@163.783,103.668 cw(c164.465,104.35) v1@163.5,104.35
  Mid-Layer 2 w0.3: 127.2,97.675 v1@128.987,95.887 ; 127.2,97.681 v1(127.2,106) 127.2,112.7 v1(133.2,118.7) 138,123.5 v1(146.25,123.5) 153,123.5 v1(158.9,117.6) 163.45,113.05 v1(163.45,104.4) 163.45,97.625 v1(157.625,91.8) 153.125,87.3 v1(138.575,87.3) ; 128.787,96.088 ccw(c129,96.302) v1@129,96
  Bottom Layer w0.6: v1(158.9,117.6) 160.025,118.725 Q4.3@160.025,119.45 ; 159.214,117.914 ccw(c157.677,119.45) Q4.3@159.85,119.45
INPUT: Q1.3 R1.1 U2.6 | length 20
  Top Layer w0.2: U2.6@146.437,111.393 147.832,111.393 148.025,111.2 149.25,111.2 150.25,112.2 v1(155,112.2) ; v1@154.894,112.094 ccw(c154.638,111.838) 154.638,112.2 ccw(c154.638,112.562) v1@154.894,112.306
  Bottom Layer w0.254: v1@155,112.077 cw(c155,111.78) 155.21,111.99 cw(c155.42,112.2) v1@155.123,112.2 ; v1(155,112.2) 156.5,110.7 R1.1@158.475,110.7 158.525,110.65 Q1.3@160.55,110.65 ; R1.1@158.247,110.472 ccw(c157.695,109.92) 157.695,110.7 ccw(c157.695,111.48) R1.1@158.247,110.928 ; R1.1@158.703,110.422 cw(c159.255,109.87) 159.255,110.65 cw(c159.255,111.43) R1.1@158.703,110.878 ; Q1.3@160.297,110.422 ccw(c159.745,109.87) 159.745,110.65 ccw(c159.745,111.43) Q1.3@160.297,110.878
LED_B: R21.2 R22.2 U2.4 | length 26.3
  Top Layer w0.2: U2.4@142.963,111.893 142.018,111.893 141.75,111.625 141.75,109.4 142.25,108.9 149.475,108.9 ; 148.83,108.9 ccw(c148.83,109.945) v1@149.569,109.206 ; 149.313,108.9 ccw(c149.313,109.462) v1@149.71,109.065 ; v1@149.528,109.072 cw(c149.339,109.036) 149.475,108.9 ; v1@149.647,108.953 ccw(c149.611,108.764) 149.475,108.9 ; v1(149.675,109.1) 149.475,108.9
  Bottom Layer w0.2: v1(149.675,109.1) 149.925,109.35 149.925,110.25 154.025,114.35 R21.2@154.075,114.35 154.025,114.4 R22.2@154.025,116.15 ; R21.2@153.675,114.35 cw(c152.83,114.35) 153.428,113.753 cw(c154.025,113.155) R21.2@154.025,114 ; R21.2@153.778,114.597 ccw(c153.18,115.195) 154.025,115.195 ccw(c154.87,115.195) R21.2@154.272,114.597 ; R22.2@153.778,115.903 cw(c153.18,115.305) 154.025,115.305 cw(c154.87,115.305) R22.2@154.272,115.903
